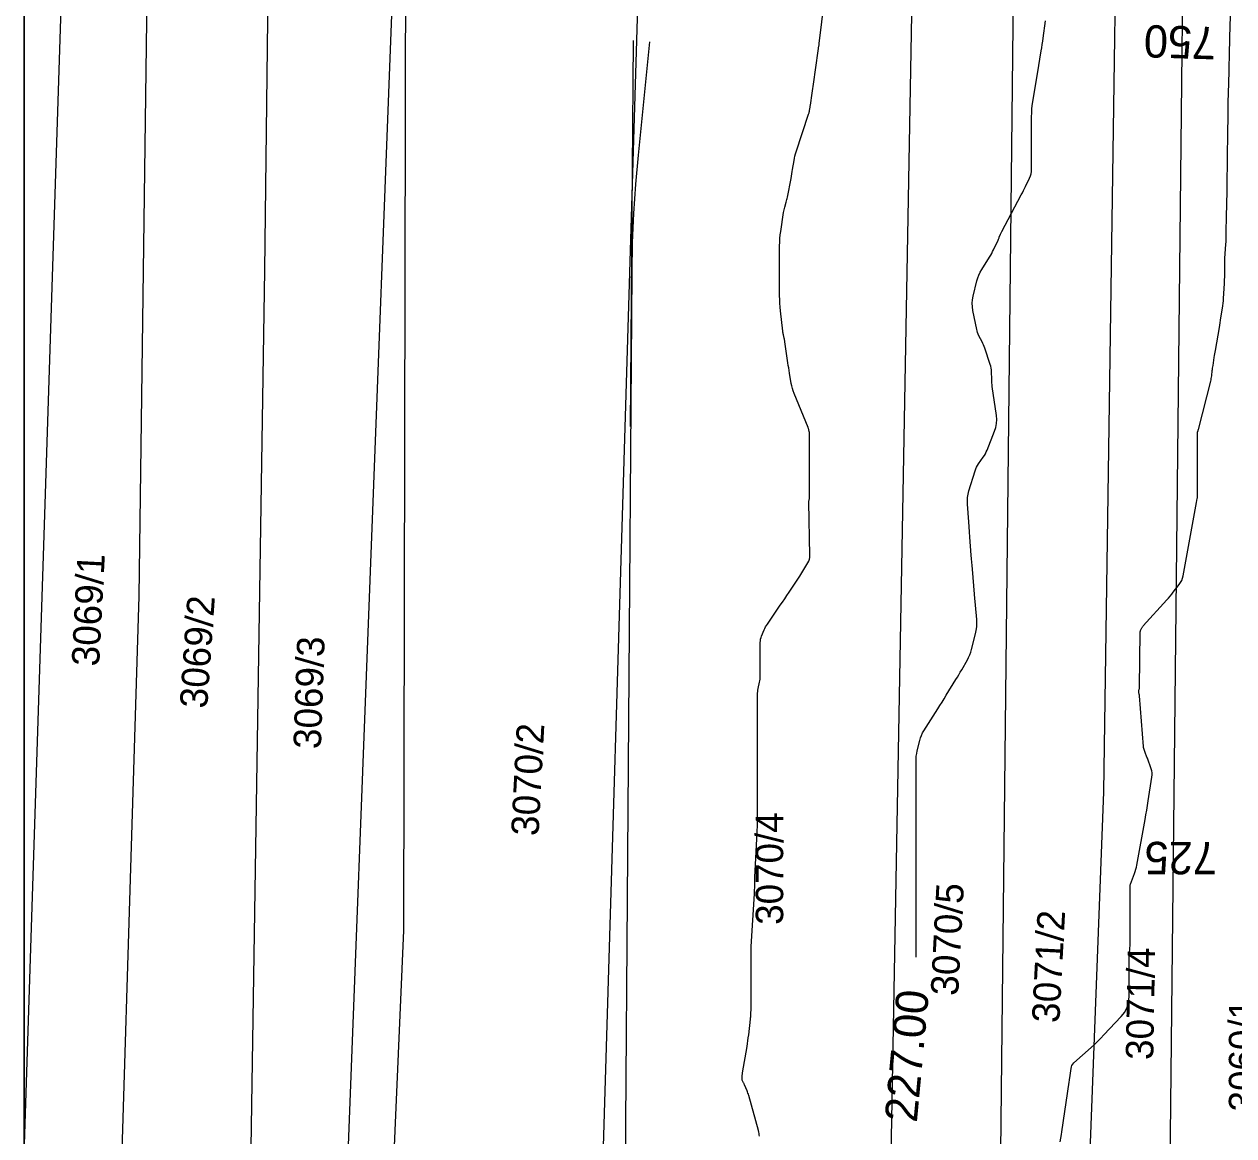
# Model space of a CAD drawing. Extents: x -534410 to -534262, y -1190162 to -1189584.
# Drawn here: x -534410.13 to -534372.72, y -1189864.58 to -1189830.22 of the extents above; entities that cross this region are included whole.
import ezdxf

# ---------------------------------------------------------------- set-up
doc = ezdxf.new("R2010")
doc.units = 0
for name, color, linetype in [('30', 7, 'Continuous'), ('31', 7, 'Continuous'), ('40', 7, 'Continuous'), ('_N_text', 7, 'Continuous'), ('_rámeček', 7, 'Continuous'), ('_rámeček_mřížka', 7, 'Continuous'), ('Hranice parcel', 7, 'Continuous'), ('Parcelní čísla', 7, 'Continuous')]:
    doc.layers.add(name, color=color, linetype=linetype)

msp = doc.modelspace()

# ---------------------------------------------------------------- linework, layer by layer
at = {"layer": '30'}
for points in [[(-534382.549, -1189859.059), (-534382.549, -1189853.012), (-534382.547, -1189852.928), (-534382.54, -1189852.846), (-534382.527, -1189852.764), (-534382.51, -1189852.682), (-534382.432, -1189852.357), (-534382.409, -1189852.278), (-534382.38, -1189852.2), (-534382.345, -1189852.126), (-534382.303, -1189852.054), (-534381.877, -1189851.384), (-534381.81, -1189851.279), (-534381.744, -1189851.173), (-534381.678, -1189851.068), (-534381.613, -1189850.961), (-534381.314, -1189850.474), (-534381.269, -1189850.399), (-534381.224, -1189850.323), (-534381.179, -1189850.247), (-534381.136, -1189850.171), (-534380.961, -1189849.866), (-534380.921, -1189849.788), (-534380.885, -1189849.709), (-534380.855, -1189849.627), (-534380.831, -1189849.543), (-534380.707, -1189849.062), (-534380.684, -1189848.953), (-534380.67, -1189848.843), (-534380.666, -1189848.732), (-534380.671, -1189848.621), (-534380.738, -1189847.85), (-534380.739, -1189847.838), (-534380.807, -1189847.058), (-534380.816, -1189846.951), (-534380.825, -1189846.844), (-534380.834, -1189846.738), (-534380.842, -1189846.631), (-534380.883, -1189846.069), (-534380.895, -1189845.912), (-534380.918, -1189845.597), (-534380.958, -1189845.052), (-534380.961, -1189844.949), (-534380.954, -1189844.847), (-534380.938, -1189844.745), (-534380.912, -1189844.645), (-534380.721, -1189844.021), (-534380.701, -1189843.963), (-534380.676, -1189843.907), (-534380.647, -1189843.853), (-534380.613, -1189843.802), (-534380.469, -1189843.6), (-534380.435, -1189843.548), (-534380.404, -1189843.495), (-534380.376, -1189843.44), (-534380.351, -1189843.383), (-534380.117, -1189842.797), (-534380.079, -1189842.679), (-534380.056, -1189842.56), (-534380.05, -1189842.438), (-534380.06, -1189842.314), (-534380.189, -1189841.421), (-534380.196, -1189841.364), (-534380.202, -1189841.306), (-534380.206, -1189841.249), (-534380.208, -1189841.191), (-534380.213, -1189840.96), (-534380.216, -1189840.903), (-534380.224, -1189840.846), (-534380.236, -1189840.79), (-534380.252, -1189840.735), (-534380.425, -1189840.228), (-534380.443, -1189840.178), (-534380.463, -1189840.13), (-534380.484, -1189840.082), (-534380.507, -1189840.034), (-534380.603, -1189839.846), (-534380.625, -1189839.799), (-534380.644, -1189839.75), (-534380.66, -1189839.7), (-534380.672, -1189839.649), (-534380.79, -1189839.066), (-534380.806, -1189838.955), (-534380.81, -1189838.845), (-534380.802, -1189838.735), (-534380.782, -1189838.625), (-534380.669, -1189838.154), (-534380.642, -1189838.061), (-534380.608, -1189837.971), (-534380.567, -1189837.884), (-534380.518, -1189837.8), (-534380.273, -1189837.414), (-534380.24, -1189837.36), (-534380.209, -1189837.305), (-534380.179, -1189837.248), (-534380.151, -1189837.191), (-534380.011, -1189836.888), (-534380.001, -1189836.866), (-534379.991, -1189836.844), (-534379.982, -1189836.822), (-534379.973, -1189836.8), (-534379.938, -1189836.711), (-534379.929, -1189836.689), (-534379.92, -1189836.667), (-534379.909, -1189836.646), (-534379.898, -1189836.625), (-534379.293, -1189835.49), (-534379.259, -1189835.426), (-534379.226, -1189835.362), (-534379.194, -1189835.298), (-534379.162, -1189835.233), (-534379.036, -1189834.974), (-534379.008, -1189834.908), (-534378.989, -1189834.841), (-534378.977, -1189834.772), (-534378.973, -1189834.7), (-534378.973, -1189833.078), (-534378.971, -1189832.961), (-534378.964, -1189832.845), (-534378.952, -1189832.73), (-534378.935, -1189832.614), (-534378.822, -1189831.924), (-534378.794, -1189831.754), (-534378.678, -1189831.042), (-534378.662, -1189830.943), (-534378.647, -1189830.844), (-534378.632, -1189830.745), (-534378.618, -1189830.646), (-534378.544, -1189830.112)], [(-534390.792, -1189830.764), (-534391.145, -1189834.263), (-534391.226, -1189835.167), (-534391.285, -1189836.071), (-534391.324, -1189836.977), (-534391.341, -1189837.885), (-534391.562, -1189868.34)]]:
    msp.add_lwpolyline(points, dxfattribs=at)
at = {"layer": '31'}
for points in [[(-534387.392, -1189864.586), (-534387.396, -1189864.543), (-534387.403, -1189864.501), (-534387.411, -1189864.459), (-534387.422, -1189864.417), (-534387.722, -1189863.328), (-534387.733, -1189863.291), (-534387.746, -1189863.254), (-534387.759, -1189863.217), (-534387.774, -1189863.182), (-534387.852, -1189862.999), (-534387.859, -1189862.984), (-534387.867, -1189862.968), (-534387.874, -1189862.952), (-534387.882, -1189862.937), (-534387.915, -1189862.875), (-534387.922, -1189862.86), (-534387.927, -1189862.844), (-534387.929, -1189862.827), (-534387.929, -1189862.81), (-534387.922, -1189862.712), (-534387.921, -1189862.69), (-534387.918, -1189862.668), (-534387.915, -1189862.646), (-534387.912, -1189862.625), (-534387.773, -1189861.813), (-534387.759, -1189861.724), (-534387.746, -1189861.636), (-534387.734, -1189861.548), (-534387.723, -1189861.459), (-534387.666, -1189860.969), (-534387.664, -1189860.948), (-534387.662, -1189860.926), (-534387.66, -1189860.904), (-534387.659, -1189860.883), (-534387.654, -1189860.796), (-534387.653, -1189860.774), (-534387.652, -1189860.753), (-534387.652, -1189860.731), (-534387.651, -1189860.709), (-534387.651, -1189858.867), (-534387.651, -1189858.856), (-534387.651, -1189858.845), (-534387.651, -1189858.833), (-534387.651, -1189858.822), (-534387.649, -1189858.773), (-534387.649, -1189858.762), (-534387.648, -1189858.75), (-534387.648, -1189858.738), (-534387.647, -1189858.726), (-534387.545, -1189857.096), (-534387.544, -1189857.071), (-534387.542, -1189857.045), (-534387.541, -1189857.02), (-534387.541, -1189856.995), (-534387.537, -1189856.895), (-534387.536, -1189856.844), (-534387.535, -1189856.794), (-534387.532, -1189856.685), (-534387.531, -1189856.659), (-534387.53, -1189856.632), (-534387.529, -1189856.605), (-534387.528, -1189856.579), (-534387.46, -1189855.203), (-534387.458, -1189855.167), (-534387.457, -1189855.131), (-534387.456, -1189855.095), (-534387.455, -1189855.06), (-534387.451, -1189854.916), (-534387.45, -1189854.88), (-534387.45, -1189854.844), (-534387.45, -1189854.809), (-534387.449, -1189854.773), (-534387.449, -1189850.942), (-534387.448, -1189850.893), (-534387.444, -1189850.845), (-534387.437, -1189850.797), (-534387.428, -1189850.749), (-534387.385, -1189850.559), (-534387.375, -1189850.512), (-534387.368, -1189850.464), (-534387.364, -1189850.415), (-534387.363, -1189850.367), (-534387.363, -1189849.328), (-534387.36, -1189849.277), (-534387.353, -1189849.227), (-534387.34, -1189849.178), (-534387.323, -1189849.13), (-534387.243, -1189848.94), (-534387.222, -1189848.893), (-534387.199, -1189848.847), (-534387.173, -1189848.803), (-534387.145, -1189848.759), (-534386.746, -1189848.177), (-534386.678, -1189848.077), (-534386.61, -1189847.978), (-534386.543, -1189847.878), (-534386.476, -1189847.778), (-534386.142, -1189847.277), (-534386.109, -1189847.226), (-534386.076, -1189847.175), (-534386.045, -1189847.124), (-534386.013, -1189847.072), (-534385.89, -1189846.863), (-534385.864, -1189846.81), (-534385.845, -1189846.755), (-534385.834, -1189846.697), (-534385.831, -1189846.638), (-534385.861, -1189844.993), (-534385.861, -1189844.978), (-534385.86, -1189844.963), (-534385.859, -1189844.948), (-534385.857, -1189844.933), (-534385.846, -1189844.874), (-534385.844, -1189844.859), (-534385.842, -1189844.844), (-534385.842, -1189844.829), (-534385.841, -1189844.814), (-534385.841, -1189842.879), (-534385.842, -1189842.862), (-534385.843, -1189842.845), (-534385.846, -1189842.828), (-534385.85, -1189842.812), (-534385.867, -1189842.746), (-534385.871, -1189842.729), (-534385.876, -1189842.713), (-534385.882, -1189842.697), (-534385.888, -1189842.681), (-534386.317, -1189841.629), (-534386.345, -1189841.553), (-534386.37, -1189841.477), (-534386.389, -1189841.4), (-534386.405, -1189841.321), (-534386.459, -1189841.003), (-534386.472, -1189840.924), (-534386.485, -1189840.844), (-534386.497, -1189840.765), (-534386.508, -1189840.685), (-534386.601, -1189840.033), (-534386.606, -1189840.006), (-534386.611, -1189839.979), (-534386.616, -1189839.952), (-534386.622, -1189839.925), (-534386.649, -1189839.818), (-534386.656, -1189839.791), (-534386.661, -1189839.764), (-534386.665, -1189839.737), (-534386.669, -1189839.709), (-534386.739, -1189839.074), (-534386.75, -1189838.959), (-534386.758, -1189838.844), (-534386.763, -1189838.729), (-534386.765, -1189838.613), (-534386.765, -1189838.111), (-534386.765, -1189837.866), (-534386.765, -1189837.621), (-534386.765, -1189837.069), (-534386.763, -1189836.957), (-534386.756, -1189836.845), (-534386.746, -1189836.733), (-534386.732, -1189836.622), (-534386.645, -1189836.036), (-534386.638, -1189835.996), (-534386.63, -1189835.956), (-534386.62, -1189835.916), (-534386.609, -1189835.876), (-534386.562, -1189835.719), (-534386.551, -1189835.68), (-534386.541, -1189835.64), (-534386.532, -1189835.6), (-534386.524, -1189835.56), (-534386.412, -1189834.982), (-534386.399, -1189834.913), (-534386.387, -1189834.844), (-534386.375, -1189834.775), (-534386.363, -1189834.706), (-534386.318, -1189834.43), (-534386.306, -1189834.361), (-534386.291, -1189834.293), (-534386.273, -1189834.226), (-534386.252, -1189834.159), (-534385.87, -1189833.002), (-534385.863, -1189832.979), (-534385.857, -1189832.956), (-534385.851, -1189832.933), (-534385.847, -1189832.909), (-534385.83, -1189832.814), (-534385.826, -1189832.79), (-534385.822, -1189832.766), (-534385.818, -1189832.742), (-534385.815, -1189832.718), (-534385.763, -1189832.348), (-534385.753, -1189832.278), (-534385.743, -1189832.209), (-534385.733, -1189832.139), (-534385.723, -1189832.069), (-534385.573, -1189831.039), (-534385.551, -1189830.888), (-534385.548, -1189830.866), (-534385.545, -1189830.844), (-534385.542, -1189830.823), (-534385.54, -1189830.801), (-534385.51, -1189830.562), (-534385.354, -1189829.289)], [(-534378.088, -1189864.767), (-534378.053, -1189864.535), (-534378.041, -1189864.457), (-534377.811, -1189862.919), (-534377.802, -1189862.857), (-534377.799, -1189862.838), (-534377.792, -1189862.782), (-534377.756, -1189862.493), (-534377.745, -1189862.445), (-534377.727, -1189862.401), (-534377.702, -1189862.361), (-534377.668, -1189862.326), (-534377.131, -1189861.844), (-534377.03, -1189861.751), (-534376.931, -1189861.656), (-534376.834, -1189861.559), (-534376.74, -1189861.46), (-534376.201, -1189860.886), (-534376.095, -1189860.751), (-534376.02, -1189860.604), (-534375.974, -1189860.445), (-534375.959, -1189860.275), (-534375.959, -1189859.161), (-534375.959, -1189859.111), (-534375.957, -1189859.061), (-534375.955, -1189859.011), (-534375.951, -1189858.961), (-534375.935, -1189858.761), (-534375.931, -1189858.711), (-534375.928, -1189858.661), (-534375.927, -1189858.611), (-534375.926, -1189858.561), (-534375.926, -1189857.074), (-534375.926, -1189857.051), (-534375.927, -1189857.028), (-534375.927, -1189857.005), (-534375.928, -1189856.982), (-534375.931, -1189856.89), (-534375.93, -1189856.868), (-534375.928, -1189856.845), (-534375.923, -1189856.823), (-534375.916, -1189856.802), (-534375.79, -1189856.466), (-534375.768, -1189856.402), (-534375.749, -1189856.338), (-534375.733, -1189856.273), (-534375.719, -1189856.207), (-534375.464, -1189854.801), (-534375.439, -1189854.657), (-534375.414, -1189854.513), (-534375.39, -1189854.369), (-534375.367, -1189854.224), (-534375.252, -1189853.491), (-534375.246, -1189853.424), (-534375.248, -1189853.358), (-534375.258, -1189853.293), (-534375.277, -1189853.229), (-534375.395, -1189852.904), (-534375.406, -1189852.874), (-534375.417, -1189852.845), (-534375.428, -1189852.815), (-534375.439, -1189852.786), (-534375.485, -1189852.668), (-534375.496, -1189852.639), (-534375.504, -1189852.609), (-534375.51, -1189852.578), (-534375.513, -1189852.547), (-534375.639, -1189850.973), (-534375.64, -1189850.96), (-534375.642, -1189850.947), (-534375.645, -1189850.934), (-534375.648, -1189850.921), (-534375.66, -1189850.87), (-534375.663, -1189850.857), (-534375.663, -1189850.845), (-534375.662, -1189850.832), (-534375.66, -1189850.819), (-534375.646, -1189850.767), (-534375.643, -1189850.754), (-534375.641, -1189850.74), (-534375.64, -1189850.727), (-534375.639, -1189850.714), (-534375.615, -1189849.009), (-534375.614, -1189848.991), (-534375.61, -1189848.974), (-534375.605, -1189848.957), (-534375.598, -1189848.941), (-534375.564, -1189848.877), (-534375.555, -1189848.861), (-534375.545, -1189848.846), (-534375.534, -1189848.831), (-534375.522, -1189848.818), (-534374.792, -1189848.011), (-534374.741, -1189847.954), (-534374.692, -1189847.896), (-534374.643, -1189847.837), (-534374.596, -1189847.778), (-534374.408, -1189847.536), (-534374.366, -1189847.474), (-534374.331, -1189847.408), (-534374.305, -1189847.339), (-534374.287, -1189847.266), (-534373.874, -1189845.001), (-534373.863, -1189844.939), (-534373.851, -1189844.876), (-534373.849, -1189844.86), (-534373.847, -1189844.844), (-534373.846, -1189844.829), (-534373.845, -1189844.813), (-534373.845, -1189842.865), (-534373.845, -1189842.855), (-534373.844, -1189842.845), (-534373.842, -1189842.834), (-534373.84, -1189842.824), (-534373.826, -1189842.774), (-534373.821, -1189842.754), (-534373.818, -1189842.744), (-534373.436, -1189841.252), (-534373.426, -1189841.212), (-534373.418, -1189841.172), (-534373.411, -1189841.131), (-534373.406, -1189841.09), (-534373.387, -1189840.926), (-534373.382, -1189840.886), (-534373.377, -1189840.845), (-534373.371, -1189840.804), (-534373.365, -1189840.763), (-534373.324, -1189840.517), (-534373.315, -1189840.462), (-534373.306, -1189840.408), (-534373.297, -1189840.353), (-534373.288, -1189840.298), (-534373.169, -1189839.594), (-534373.156, -1189839.519), (-534373.144, -1189839.444), (-534373.131, -1189839.369), (-534373.119, -1189839.294), (-534373.071, -1189838.994), (-534373.059, -1189838.919), (-534373.05, -1189838.844), (-534373.043, -1189838.769), (-534373.038, -1189838.693), (-534373.011, -1189838.235), (-534373.008, -1189838.17), (-534373.006, -1189838.105), (-534373.004, -1189838.04), (-534373.004, -1189837.975), (-534373.004, -1189837.714), (-534373.003, -1189837.649), (-534373.002, -1189837.584), (-534372.999, -1189837.519), (-534372.996, -1189837.454), (-534372.968, -1189837.029), (-534372.963, -1189836.937), (-534372.959, -1189836.844), (-534372.955, -1189836.752), (-534372.954, -1189836.659), (-534372.946, -1189836.144), (-534372.945, -1189836.095), (-534372.944, -1189836.046), (-534372.943, -1189835.997), (-534372.942, -1189835.948), (-534372.936, -1189835.752), (-534372.935, -1189835.703), (-534372.934, -1189835.654), (-534372.933, -1189835.605), (-534372.932, -1189835.556), (-534372.925, -1189835.047), (-534372.924, -1189834.946), (-534372.923, -1189834.844), (-534372.921, -1189834.743), (-534372.92, -1189834.642), (-534372.914, -1189834.097), (-534372.913, -1189834.056), (-534372.912, -1189834.014), (-534372.912, -1189833.973), (-534372.911, -1189833.931), (-534372.907, -1189833.765), (-534372.906, -1189833.724), (-534372.905, -1189833.683), (-534372.905, -1189833.641), (-534372.904, -1189833.6), (-534372.898, -1189833.054), (-534372.896, -1189832.949), (-534372.895, -1189832.845), (-534372.893, -1189832.74), (-534372.891, -1189832.635), (-534372.878, -1189832.042), (-534372.877, -1189832.01), (-534372.876, -1189831.978), (-534372.875, -1189831.945), (-534372.874, -1189831.913), (-534372.869, -1189831.785), (-534372.868, -1189831.753), (-534372.867, -1189831.721), (-534372.866, -1189831.689), (-534372.865, -1189831.657), (-534372.852, -1189831.064), (-534372.85, -1189830.954), (-534372.847, -1189830.845), (-534372.844, -1189830.735), (-534372.841, -1189830.625), (-534372.82, -1189829.956)], [(-534391.375, -1189842.65), (-534391.289, -1189830.721)]]:
    msp.add_lwpolyline(points, dxfattribs=at)
at = {"layer": '_rámeček'}
msp.add_line((-534410.126, -1189584.47), (-534410.126, -1190161.97), dxfattribs=at)
msp.add_lwpolyline([(-534410.126, -1189794.47), (-534261.626, -1189794.47), (-534261.626, -1189899.47), (-534410.126, -1189899.47)], close=True, dxfattribs=at)
at = {"layer": '_rámeček_mřížka'}
msp.add_line((-534410.126, -1189584.47), (-534410.126, -1190161.97), dxfattribs=at)
at = {"layer": 'Hranice parcel'}
for p, q in [((-534410.126, -1189865.16), (-534408.06, -1189801.17)), ((-534403.19, -1189945.91), (-534398.3, -1189817.87))]:
    msp.add_line(p, q, dxfattribs=at)
for points in [[(-534395.93, -1189955.06), (-534393.76, -1189916.2), (-534389.49, -1189774.63), (-534390.92, -1189749.37)], [(-534385.61, -1189919.11), (-534380.06, -1189877.29), (-534378.67, -1189750.28)], [(-534385.61, -1189919.11), (-534383.81, -1189892.54), (-534382.22, -1189804.86), (-534381.85, -1189775.86), (-534383.09, -1189750.44)], [(-534383.94, -1189956.8), (-534379.19, -1189918.48), (-534376.74, -1189853.94), (-534375.92, -1189797.44), (-534376.41, -1189774.02), (-534378.12, -1189750.26)], [(-534406.13, -1189942), (-534403.45, -1189886.77), (-534402.68, -1189837.82), (-534401.95, -1189776.76), (-534406.3, -1189754), (-534406.48, -1189752.31)], [(-534373.61, -1189764.09), (-534375.04, -1189897.07), (-534384.28, -1189963.65)], [(-534410.126, -1189932.794), (-534408.16, -1189899.66), (-534406.57, -1189847.9), (-534405.68, -1189781.38), (-534406.95, -1189766.9)], [(-534403.19, -1189945.91), (-534400.52, -1189907.49), (-534398.39, -1189858.23), (-534398.3, -1189817.87)]]:
    msp.add_lwpolyline(points, dxfattribs=at)

# ---------------------------------------------------------------- texts
at = {"layer": '40'}
msp.add_text('227.00', height=1, rotation=84.6806, dxfattribs=at).set_placement((-534382.524, -1189864.186))
at = {"layer": '_N_text'}
for s, rotation, p in [('750', 178.2276, (-534373.254, -1189830.308)), ('725', 179.8487, (-534373.247, -1189855.495))]:
    msp.add_text(s, height=1, rotation=rotation, dxfattribs=at).set_placement(p)
at = {"layer": 'Parcelní čísla'}
for s, rotation, p in [('3069/1', 87, (-534407.812, -1189850.078)), ('3069/2', 86, (-534404.47, -1189851.381)), ('3069/3', 88, (-534400.953, -1189852.63)), ('3070/2', 87, (-534394.222, -1189855.322)), ('3070/4', 90, (-534386.656, -1189858.055)), ('3070/5', 87, (-534381.247, -1189860.26)), ('3071/2', 87, (-534378.118, -1189861.101)), ('3071/4', 89, (-534375.214, -1189862.236)), ('3060/1', 90, (-534372.025, -1189863.823))]:
    msp.add_text(s, height=0.85, rotation=rotation, dxfattribs=at).set_placement(p)

doc.saveas('drawing.dxf')
